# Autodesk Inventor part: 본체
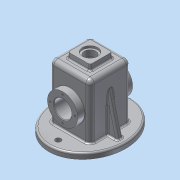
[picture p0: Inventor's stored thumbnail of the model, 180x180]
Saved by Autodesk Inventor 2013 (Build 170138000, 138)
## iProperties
Created: 2017-07
Part Number: 본체
Material: 알루미늄 6061
Document SubType Name: Modeling
Designer: Administrator
Density: 1 g/cm^3
Author: Administrator
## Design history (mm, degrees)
sketch "스케치1"
  geometry: L1 (-37, -37)-(37, -37); L2 (37, -37)-(37, 37); L3 (37, 37)-(-37, 37); L4 (-37, 37)-(-37, -37); L5 (-37, -37)-(37, 37); L6 (37, -37)-(-37, 37); 1 further point
  constraints: 12 end point, 2 midpoint, 2 parallel, 1 horizontal, 1 perpendicular
  dimensions: "d0" = 74 distance of L2.end L3.end; "d2" = 74 distance of L3.end L1.start
extrude "돌출1" new body sketch "스케치1" distance "d3" = 100; taper "d4" = 0 deg
feature "쉘1" dims "d5" = 5
node "작업 평면1"
sketch "스케치3" dims "d17" = 75
  geometry: L1 (0, 0)-(-65, 0); 1 further point; 1 other entity
  constraints: 2 end point, 1 coincident, 1 horizontal, 1 horizontal alignment, 2 other
  dimensions: "d25" = 65 distance of point (0, 0) L1.end
extrude "돌출5" join sketch "스케치3" distance "d19" = 10; taper "d20" = 0 deg
sketch "스케치9"
  geometry: L1 (-37, -37)-(-37, 37) reference; L2 (-37, 37)-(37, 37) reference; L3 (37, 37)-(37, -37) reference; L4 (37, -37)-(-37, -37) reference
extrude "돌출6" cut sketch "스케치9" distance "d21" = 10; taper "d22" = 0 deg
sketch "스케치10"
  geometry: L1 (32, -32)-(-32, -32) reference; L2 (-32, -32)-(-32, 32) reference; L3 (-32, 32)-(32, 32) reference; L4 (32, 32)-(32, -32) reference; L5 (-37, -37)-(-37, 37) reference; L6 (37, -37)-(-37, -37) reference; L7 (37, 37)-(37, -37) reference; L8 (-37, 37)-(37, 37) reference; 1 further point
extrude "돌출7" join sketch "스케치10" distance "d23" = 10; taper "d24" = 0 deg
sketch "스케치11"
  geometry: L1 (-32, -32)-(32, -32) reference; L2 (-32, 32)-(-32, -32) reference; L3 (32, 32)-(-32, 32) reference; L4 (32, -32)-(32, 32) reference; C1 r 5 at (0, -58); C2 r 5 at (0, 58); 1 further point; 1 other entity
  constraints: 2 centre point, 2 vertical alignment, 1 other
  dimensions: "d26" = 10 diameter of C1; "d28" = 10 diameter of C2; "d29" = 58 distance of point (0, 0) C1.centre; "d30" = 58 distance of point (0, 0) C2.centre
extrude "돌출8" cut sketch "스케치11" distance "d31" = 10; taper "d32" = 0 deg
node "작업 평면2"
sketch "스케치15"
  geometry: L1 (-20, -20)-(20, -20); L2 (20, -20)-(20, 20); L3 (20, 20)-(-20, 20); L4 (-20, 20)-(-20, -20); L5 (-20, -20)-(20, 20); L6 (20, -20)-(-20, 20); 1 further point
  constraints: 12 end point, 2 midpoint, 2 parallel, 1 horizontal, 1 perpendicular
  dimensions: "d41" = 40 distance of L2.end L3.end; "d43" = 40 distance of L3.end L1.start
extrude "돌출9" join sketch "스케치15" stored distance "d44" = 10; taper "d45" = 5 deg
sketch "스케치16"
  geometry: C1 r 14 at (0, 0); 1 further point
  constraints: 1 centre point, 1 coincident
  dimensions: "d46" = 28 diameter of C1
extrude "돌출10" cut sketch "스케치16" distance "d48" = 4; taper "d49" = 0 deg
sketch "스케치17"
  geometry: C1 r 14 at (0, 0) reference; C2 r 10.5 at (0, 0)
  constraints: 1 centre point, 1 coincident
  dimensions: "d50" = 21 diameter of C2
extrude "돌출11" cut sketch "스케치17" stored distance "d52" = 4; taper "d53" = 0 deg
node "작업 평면3"
fillet "모깎기1" dims "d62" = 3
sketch "스케치23"
  geometry: L1 (-37, 0)-(-37, 100) reference; L2 (-32, -10)-(-32, 95) reference; L3 (-37, 45)-(0.546, 45); L4 (-75, -10)-(75, -10) reference; L5 (10.5, 95)-(-10.5, 95) reference; L6 (0, 95)-(0, 82.286); L7 (-50, 72.5)-(-32, 72.5); L8 (-32, 72.5)-(-25, 65.5); L9 (-25, 65.5)-(-25, 61); L10 (-25, 61)-(-50, 61); L11 (-50, 61)-(-50, 72.5); 1 further point
  constraints: 14 end point, 5 perpendicular, 2 point on line, 1 midpoint, 1 parallel
  dimensions: "d64" = 55 distance between parallel lines of L4 L3; "d77" = 50 distance between parallel lines of L6 L11; "d78" = 55 diameter of L7 L3; "d79" = 32 diameter of L10 L3; "d80" = 135 deg angle of L2 L8; "d81" = 7 distance from line of L7.end L9
revolve "회전3" stored, may be unused: angle "d82" = 90 deg
fillet "모깎기4" dims "d84" = 8
node "작업 평면4"
sketch "스케치27"
  geometry: C1 r 16 at (0, 0) reference; 1 further point
extrude "돌출14" cut sketch "스케치27" stored distance "d85" = 4; taper "d86" = 0 deg
sketch "스케치28"
  geometry: C1 r 16 at (0, 0) reference; 1 further point
extrude "돌출15" cut sketch "스케치28" stored distance "d87" = 4; taper "d88" = 0 deg
fillet "모깎기5" dims "d89" = 3
sketch "스케치29" dims "d90" = 45
  geometry: C1 r 27.5 at (0, 0) reference; C2 r 16 at (0, 0) reference; 3 further points
  constraints: 2 vertical alignment, 1 coincident, 2 other
hole "구멍1" sketch "스케치29" at (0, 22.5) diameter "d92" = 3.242; stored, may be unused: countersink angle "d96" = 90 deg, drill point angle "d98" = 118 deg; dims "d93" = 8, "d94" = 4, "d95" = 2, "d97" = 10
sketch "스케치30" dims "d102" = 45
  geometry: C1 r 27.5 at (0, 0) reference; C2 r 16 at (0, 0) reference; 3 further points
  constraints: 2 vertical alignment, 1 coincident, 2 other
hole "구멍2" sketch "스케치30" at (0, -22.5) diameter "d104" = 3.242; stored, may be unused: countersink angle "d108" = 90 deg, drill point angle "d110" = 118 deg; dims "d105" = 8, "d106" = 4, "d107" = 2, "d109" = 10
chamfer "모따기1" distance "d114" = 1; stored, may be unused: second distance "d115" = 2, angle "d116" = 45 deg
fillet "모깎기6" dims "d117" = 0.5
sketch "스케치33"
  geometry: L1 (-37, 0)-(-37, 92) reference; L2 (37, 92)-(37, 0) reference; L3 (-65, -10)-(65, -10) reference; L4 (-65, -10)-(-65, -1.67); L5 (-37, 0)-(-62.711, 0); L6 (-37, 72.194)-(-55, 0); L7 (65, -10)-(65, -0.628); L8 (37, 0)-(64.107, 0); L9 (37, 72.194)-(55, 0); 1 further point
  constraints: 12 end point, 4 perpendicular, 4 point on line
  dimensions: "d124" = 10 distance from line of L4 L6.end; "d126" = 14 deg angle of L4 L6; "d128" = 10 distance from line of L7 L9.end; "d129" = 14 deg angle of L7 L9
extrude "돌출16" join sketch "스케치33" stored distance "d130" = 10; taper "d131" = 0 deg
fillet "모깎기7" dims "d132" = 3
node "작업 평면6"
sketch "스케치36"
  geometry: L1 (-20.739, 83.002)-(20.739, 83.002); L2 (20.739, 83.002)-(20.739, 76.998); L3 (20.739, 76.998)-(-20.739, 76.998); L4 (-20.739, 76.998)-(-20.739, 83.002); L5 (-20.739, 80)-(20.739, 80); L6 (0, 83.002)-(0, 76.998); L7 (-17.011, 110)-(17.011, 110) reference; L8 (37, 3)-(37, 92) reference; 1 further point
  constraints: 4 end point, 4 midpoint, 2 other
  dimensions: "d141" = 37 distance from line of L8 L6.start; "d142" = 30 distance between parallel lines of L7 L5
extrude "돌출18" join sketch "스케치36" distance "d143" = 0.5; taper "d144" = 0 deg
node "솔리드1"
mirror "대칭2"
pattern_circular "원형 패턴1" dims angle "d100" = 360 deg
pattern_circular "원형 패턴2" dims angle "d112" = 360 deg
other parameters: "d138" = 37.5
